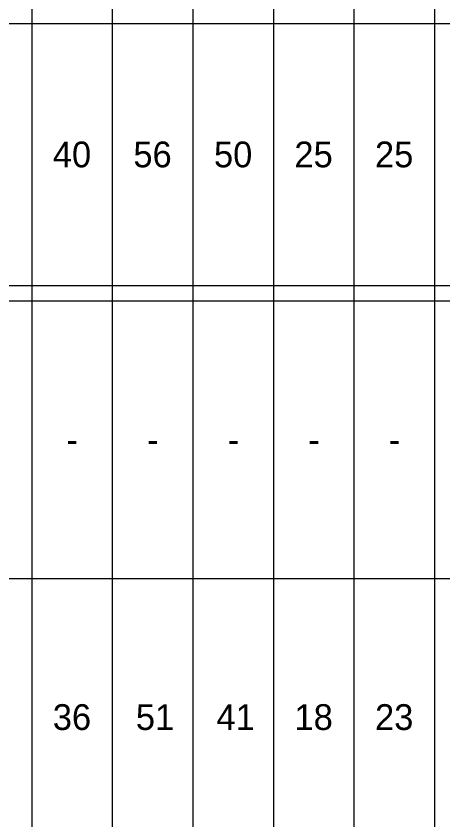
# Model space of a CAD drawing. Extents: x 0 to 0.83, y -0.65 to 1.27.
# Drawn here: x 0.6168 to 0.7272, y 0.655 to 0.8629 of the extents above; entities that cross this region are included whole.
import ezdxf

# ---------------------------------------------------------------- set-up
doc = ezdxf.new("R2010")
doc.units = 0

msp = doc.modelspace()

# ---------------------------------------------------------------- linework, layer by layer
for points in [[(0.6625, 1.22083), (0.6625, -0.64575)], [(0.725, 1.22083), (0.725, -0.64575)], [(0.62083, 1.20833), (0.62083, -0.64575)], [(0.64167, 1.20833), (0.64167, -0.64575)], [(0.68333, 1.20833), (0.68333, -0.64575)], [(0.70417, 1.20833), (0.70417, -0.64575)], [(0.725, 1.20833), (0.725, -0.64575)], [(0.6, 0.861), (0.62083, 0.861)], [(0.62083, 0.861), (0.64167, 0.861)], [(0.64167, 0.861), (0.6625, 0.861)], [(0.6625, 0.861), (0.68333, 0.861)], [(0.68333, 0.861), (0.70417, 0.861)], [(0.70417, 0.861), (0.725, 0.861)], [(0.725, 0.861), (0.75, 0.861)], [(0.6, 0.79323), (0.62083, 0.79323)], [(0.62083, 0.79323), (0.64167, 0.79323)], [(0.64167, 0.79323), (0.6625, 0.79323)], [(0.6625, 0.79323), (0.68333, 0.79323)], [(0.68333, 0.79323), (0.70417, 0.79323)], [(0.70417, 0.79323), (0.725, 0.79323)], [(0.725, 0.79323), (0.75, 0.79323)], [(0.6, 0.78925), (0.62083, 0.78925)], [(0.62083, 0.78925), (0.64167, 0.78925)], [(0.64167, 0.78925), (0.6625, 0.78925)], [(0.6625, 0.78925), (0.68333, 0.78925)], [(0.68333, 0.78925), (0.70417, 0.78925)], [(0.70417, 0.78925), (0.725, 0.78925)], [(0.725, 0.78925), (0.75, 0.78925)], [(0.6, 0.7175), (0.62083, 0.7175)], [(0.62083, 0.7175), (0.64167, 0.7175)], [(0.64167, 0.7175), (0.6625, 0.7175)], [(0.6625, 0.7175), (0.68333, 0.7175)], [(0.68333, 0.7175), (0.70417, 0.7175)], [(0.70417, 0.7175), (0.725, 0.7175)], [(0.725, 0.7175), (0.75, 0.7175)]]:
    msp.add_lwpolyline(points)

# ---------------------------------------------------------------- texts
for s, height, p in [('40', 0.006667, (0.62629, 0.82378)), ('56', 0.006667, (0.64712, 0.82378)), ('50', 0.006667, (0.66796, 0.82378)), ('25', 0.006667, (0.68876, 0.82378)), ('25', 0.006667, (0.70959, 0.82378)), ('-', 0.00667, (0.62984, 0.75004)), ('-', 0.00667, (0.65068, 0.75004)), ('-', 0.00667, (0.67151, 0.75004)), ('-', 0.00667, (0.69234, 0.75004)), ('-', 0.00667, (0.71318, 0.75004)), ('36', 0.006667, (0.62628, 0.67829)), ('51', 0.006667, (0.64776, 0.67829)), ('41', 0.006667, (0.66859, 0.67829)), ('18', 0.006667, (0.68878, 0.67829)), ('23', 0.006667, (0.70961, 0.67829))]:
    msp.add_text(s, height=height).set_placement(p)

doc.saveas('drawing.dxf')
